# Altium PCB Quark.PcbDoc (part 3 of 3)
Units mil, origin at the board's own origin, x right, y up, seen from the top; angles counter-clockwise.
Board outline 1220.47 x 944.88 mil, 6 copper layers (Top1, Signal2, Gnd3, Power4, Signal5, Bottom6), stack 32.534 mil thick; 106 components, 182 nets, 776 pads, 404 vias.
Unrouted connection lines stored in the file: 82.
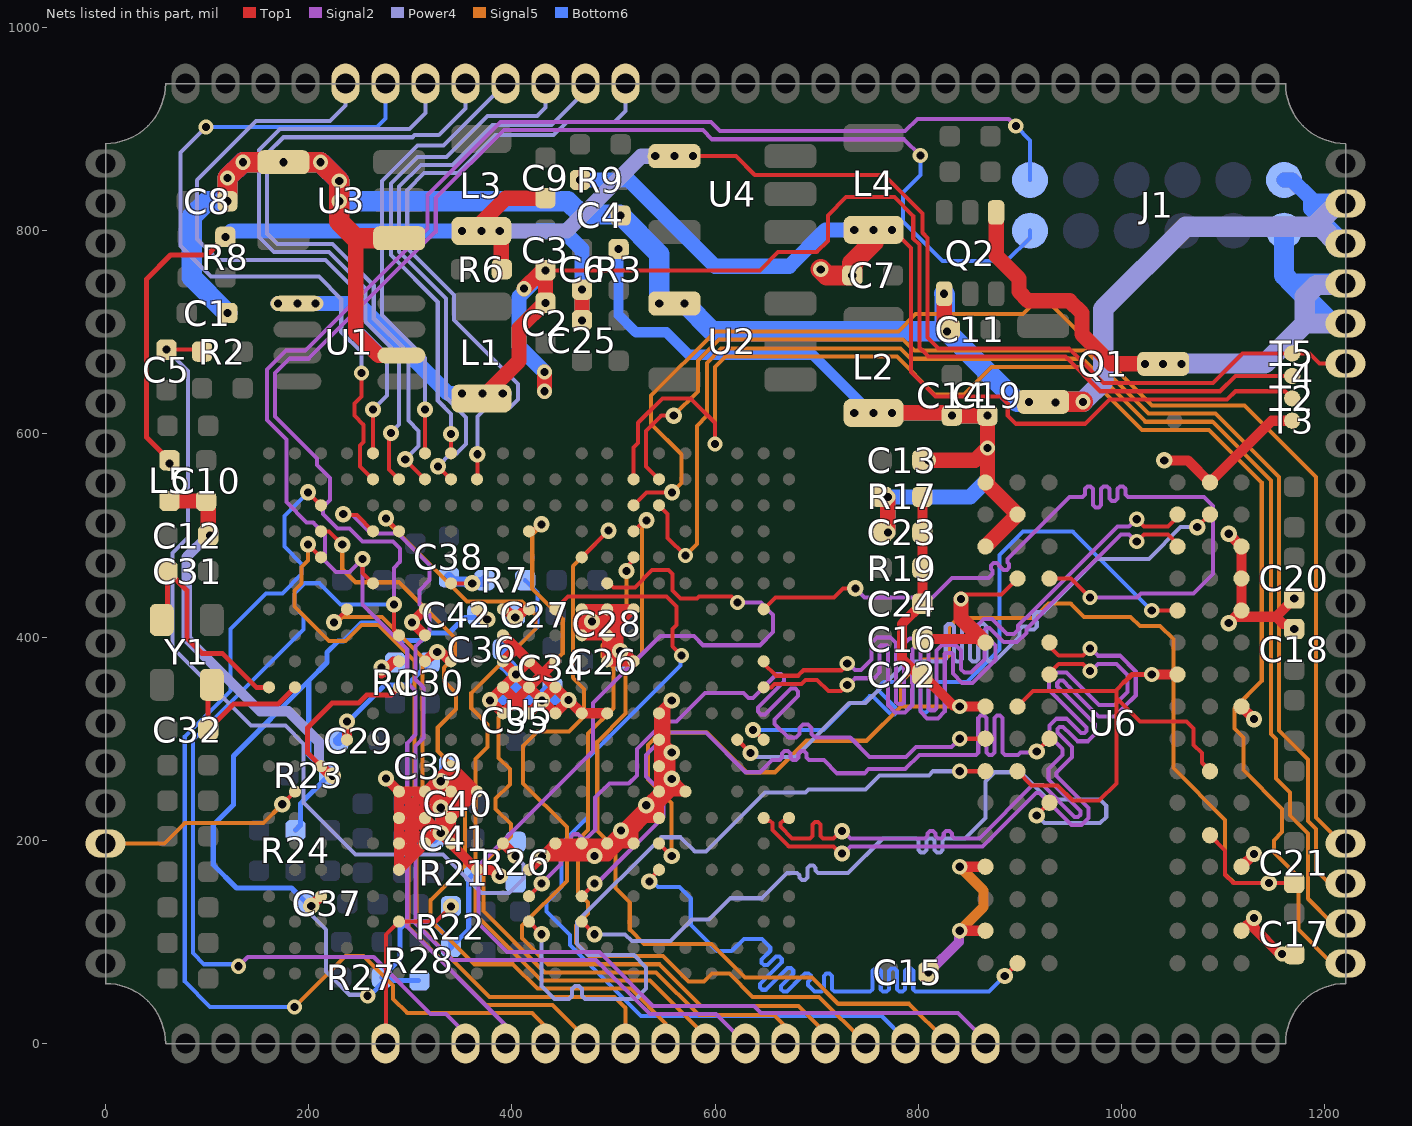
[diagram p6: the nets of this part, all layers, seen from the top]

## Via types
v1: diameter 16, hole 8, Top1 to Bottom6, tented both sides, 238 vias
v2: diameter 15, hole 8, Top1 to Bottom6, tented both sides, 166 vias

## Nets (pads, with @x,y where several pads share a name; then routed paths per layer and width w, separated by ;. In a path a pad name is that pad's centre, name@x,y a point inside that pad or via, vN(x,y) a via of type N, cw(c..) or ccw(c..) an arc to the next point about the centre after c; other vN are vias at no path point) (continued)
SDQ15: U5.M19 U6.B8 | length 793.5
  Top1 w4: U5.M19@621.77,299 v1(634.77,286) ; v1(1074.5,508.22) U6.B8@1087,520.72
  Power4 w4: v1(634.77,286) 638.77,282 679,282 732,335 748,335 789,376 823,376 824.6,376 827,378.4 827,410.6 829.4,413 832.6,413 835,410.6 835,378.4 837.4,376 840.6,376 843,378.4 843,410.6 845.4,413 848.6,413 851,410.6 851,378.4 853.4,376 856.6,376 859,378.4 859,410.6 861.4,413 864.6,413 867,410.6 867,378.4 869.4,376 870,376 875,376 897.5,398.5 899.62,400.62 899.62,403.45 899.62,407.69 902.45,410.52 906.69,410.52 908.11,409.11 909.52,407.69 913.76,407.69 916.59,410.52 916.59,414.76 915.18,416.18 913.76,417.59 913.76,421.83 916.59,424.66 920.83,424.66 921,424.5 923.5,424.5 976,477 1027,477 1058.22,508.22 v1(1074.5,508.22)
SDQM0: U5.M20 U6.E7 | length 757.4
  Top1 w4: v1@635.27,311.5 U5.M20@647.77,299 ; v2(1029.73,426.24) U6.E7@1055,426.24
  Bottom6 w4: v1(637.27,308.5) 706.5,308.5 733,335 739,335 743,335 745,335 747.83,337.83 751.79,341.79 755.18,341.79 773,323.97 776.4,323.97 778.66,326.23 778.66,329.63 760.84,347.45 760.84,350.84 764.8,354.8 766,356 770,356 778,356 783.6,356 786,353.6 786,332.8 788.4,330.4 791.6,330.4 794,332.8 794,353.6 796.4,356 799.6,356 802,353.6 802,328.4 804.4,326 807.6,326 810,328.4 810,353.6 812.4,356 815,356 848,356 880,388 880,481 903,504 951.97,504 v2(1029.73,426.24)
SDQM1: U5.G20 U6.D3 | length 839
  Top1 w4: U5.G20@647.77,427.36 659.41,439 717,439 726,448 v1(738,448) ; U6.D3@929.01,457.73 950.27,457.73 v2(969,439)
  Signal2 w4: v1(738,448) 747,439 814,439 833,458 869,458 872,461 873.13,462.13 873.13,465.53 871.56,467.1 871.56,470.49 873.82,472.75 877.22,472.75 880.49,469.49 883.75,466.22 887.15,466.22 889.41,468.48 889.41,471.87 887.84,473.45 887.84,476.84 890.76,479.76 949,538 961.6,538 964,540.4 964,546.04 966.4,548.44 969.6,548.44 972,546.04 972,529.96 974.4,527.56 977.6,527.56 980,529.96 980,546.04 982.4,548.44 985.6,548.44 988,546.04 988,536.31 990.4,533.91 993.6,533.91 996,536.31 996,546.04 998.4,548.44 1001.6,548.44 1004,546.04 1004,540.4 1006.4,538 1081,538 1090,529 1090,462 1071,443 1019,443 1015,439 v2(969,439)
SDQS0_N: U5.R21 U6.G3 | length 831.8
  Top1 w4: U5.R21@672.77,222 670.61,222 667.79,219.19 666.61,219.19 664.27,216.84 664.27,213.53 675.8,202 693.4,202 695.8,204.4 695.8,215.6 698.2,218 701.4,218 703.8,215.6 703.8,204.4 706.2,202 716.66,202 723.66,209 v1(725,209) ; U6.G3@929.01,361.96 U6.G3@929.01,363.24 929.01,364.53 938.19,373.71 962.01,373.71 v2(969.03,366.69)
  Signal2 w4: v1(725,209) 726.34,209 733.34,202 805,202 806.6,202 809,204.4 809,206.6 811.4,209 814.6,209 817,206.6 817,204.4 819.4,202 822.6,202 825,204.4 825,206.6 827.4,209 830.6,209 833,206.6 833,204.4 835.4,202 841,202 845,202 860,202 912.4,254.4 922.51,254.4 953.9,223.01 957.38,223.01 959.56,225.19 959.56,228.66 928.16,260.06 928.16,270.16 942,284 942,289.66 928.94,302.72 928.94,312.82 935.81,319.69 945.91,319.69 960.06,305.54 963.54,305.54 965.72,307.72 965.72,311.19 935.74,341.17 928.74,348.17 928.74,358.28 935.61,365.15 945.71,365.15 952.71,358.15 977.85,333 993,333 1006,346 1006,362.69 995,373.69 976.87,373.69 969.87,366.69 v2(969.03,366.69)
SDQS0_P: U5.R20 U6.F3 | length 831.8
  Top1 w4: U5.R20@647.77,222 649.94,222 652.75,219.19 653.93,219.19 656.27,216.84 656.27,210.22 672.49,194 716.66,194 723.66,187 v1(725,187) ; U6.F3@929.01,393.46 929.01,390.9 938.19,381.71 962.01,381.71 v2(968.98,388.69)
  Signal2 w4: v1(725,187) 726.34,187 733.34,194 863.31,194 915.72,246.4 919.19,246.4 950.59,215.01 960.69,215.01 967.56,221.88 967.56,231.98 936.16,263.37 936.16,266.85 951.09,281.78 951.09,291.88 936.94,306.03 936.94,309.5 939.12,311.69 942.6,311.69 950.28,304 956.75,297.54 966.85,297.54 973.31,304 973.72,304.4 973.72,314.51 943.74,344.49 936.74,351.49 936.74,354.96 938.92,357.15 942.39,357.15 949.39,350.15 977.54,322 993.31,322 1001.97,330.66 1014,342.69 1014,366 998.31,381.69 976.83,381.69 969.83,388.69 v2(968.98,388.69)
SDQS1_N: U5.J20 U6.B7 | length 832.2
  Top1 w4: U5.J20@647.77,376.18 647.77,374.23 660,362 681.81,362 687.19,367.39 724.39,367.39 v2@730,373 ; v2(1014.98,516) 1022,508.98 1045.81,508.98 1055,518.16 U6.B7@1055,520.72
  Signal2 w4: v2(730,374) 731.34,374 737.84,367.5 743.5,367.5 754,378 754,394.04 759.54,399.58 772.46,399.58 778,394.04 778,336.27 780.27,334 783.73,334 786,336.27 786,393.15 791.54,398.69 804.46,398.69 810,393.15 810,330 812,328 816,328 818,330 818,386.91 823.54,392.45 836.46,392.45 842,386.91 842,368.36 845.36,365 852,365 854.5,367.5 865,378 865,391.43 855.4,401.03 855.4,408.87 864.53,418 872.37,418 882.64,407.73 887.37,403 894,403 898.39,407.39 898.26,411.26 912.84,425.84 919.79,432.79 996,509 1007.13,509 1014.13,516 v2(1014.98,516)
SDQS1_P: U5.K20 U6.C7 | length 831.9
  Top1 w4: U5.K20@647.77,350.59 655.23,350.59 658.64,354 685.12,354 689.12,358 700.39,358 711.39,347 724,347 v2(730,353) ; v2(1015.02,494) 1022,500.98 1045.81,500.98 1055,491.79 U6.C7@1055,489.23
  Signal2 w4: v2(730,353) 731.34,353 737.84,359.5 756.46,359.5 762,365.04 762,390.73 ; 762.86,391.58 769.14,391.58 ; 770,390.73 770,332.96 776.96,326 787.04,326 794,332.96 794,387.84 796.16,390 799.84,390 802,387.84 802,326.69 808.69,320 819.31,320 826,326.69 826,383.6 ; 826.86,384.45 833.14,384.45 ; 834,383.6 834,364 843,355 853.31,355 876,377.69 876,391.74 864,403.74 864,406.16 866.84,409 870.05,409 884.05,395 897.31,395 906.39,404.07 906.39,408.07 916.15,417.84 927.79,429.47 999.31,501 1007.18,501 1014.18,494 v2(1015.02,494)
SODT0: U5.W11 U6.K1 | length 794.5
  Top1 w4: U5.W11@416.77,120 v1(429.27,107.5) ; v2(840.75,268) U6.K1@866.02,268
  Power4 w4: v1(429.27,107.5) 429.27,56.73 442,44 454,44 456,44 459,47 459,53.75 462,56.75 466,56.75 469,53.75 469,47 472,44 477,44 522,44 532,54 532,75 520,87 475,87 464,98 464,120 547,203 565.97,203 579.97,189 591,189 649,247 689,247 692,250 748,250 762,264 810.31,264 814.31,268 v2(840.75,268)
SODT1: U5.V11 U6.J1 | length 813.4
  Top1 w4: U5.V11@416.77,145 v1(429.27,157.5) ; v2(840.75,300) U6.J1@866.02,300
  Signal2 w4: v1(429.27,157.5) 446.39,174.61 448.06,176.29 448.06,180.53 443.82,184.77 443.82,189.02 446.64,191.84 450.89,191.84 457.25,185.48 460.23,182.5 464.47,182.5 467.3,185.33 467.3,189.57 464.32,192.55 457.96,198.91 457.96,203.16 460.79,205.99 465.03,205.99 469.27,201.74 473.51,201.74 478.46,206.69 482,210.23 482,242 496,256 515,256 523,264 523,290 550,317 562,317 590,345 628,345 631.5,341.5 632.91,340.09 637.16,340.09 660.53,363.46 664.77,363.46 667.6,360.63 667.6,356.39 642.11,330.89 642.11,326.87 645.15,323.82 649.18,323.82 674.67,349.32 678.91,349.32 681.74,346.49 681.74,342.25 658.37,318.87 658.37,314.63 660.5,312.5 672,301 677,301 679.4,301 683,304.6 683,310.4 686.6,314 691.4,314 695,310.4 695,304.6 698.6,301 707,301 709,301 733,301 752,282 787.69,282 797.69,292 832.75,292 v2(840.75,300)
SPI0_CLK: pad.52 U5.B16 | length 1223.8
  Top1 w4: U5.B16@544.77,555.32 532,568.09 532,603 547,618 v1(559.24,618)
  Signal5 w4: v1(559.24,618) 583,641.76 583,672.31 603.69,693 785,693 796,682 964.69,682 1026.69,620 1092.63,620 1155,557.63 1155,308 1183.5,279.5 1183.5,219.19 1191.5,211.19 1191.5,170.5 1201.66,160.34 1217.62,160.34 pad.52@1220.47,157.48
SPI0_CS: pad.50 U5.B15 | length 1410.3
  Top1 w4: U5.B15@519.77,555.32 519.77,586.77 524,591 524,611 548,635 576,635 600,611 v2(600,590)
  Signal5 w4: v2(600,590) 600,666 610,676 779,676 816,639 845,639 872,666 958.06,666 1020.06,604 1086,604 1138,552 1138,357 1111,330 1111,310 1120,301 1120,269 1158,231 1158,208 1150,200 1150,188 1174,164 1174,112 1207.26,78.74 pad.50@1220.47,78.74
SPI0_MISO: pad.51 U5.C16 | length 1347.2
  Top1 w4: U5.C16@544.77,529.72 553.3,521.2 553.3,497.77 v2(570.77,480.3)
  Signal5 w4: v2(570.77,480.3) 582,491.53 582,608 592,618 592,670 606,684 782.31,684 792.31,674 961.37,674 1023.37,612 1089.31,612 1147,554.31 1147,304.69 1152,299.69 1152,261 1166,247 1166,224.41 1183.5,206.91 1183.5,142.5 1207.89,118.11 pad.51@1220.47,118.11
SPI0_MOSI: pad.53 U5.C15 | length 1290.9
  Top1 w4: U5.C15@519.77,529.72 532.27,542.22 557.32,542.22 v1(557.65,542.52)
  Signal5 w4: v1(557.65,542.52) 567,551.87 567,580 537,610 537,637.69 600.31,701 780.31,701 797.31,718 903,718 912,727 931,727 1030,628 1121,628 1191.5,557.5 1191.5,222.5 1217.15,196.85 pad.53@1220.47,196.85
SRAS: U5.V13 U6.J3 | length 794.7
  Top1 w4: U5.V13@468.77,145 v1(481.27,157.5) ; v1(916.51,287.5) U6.J3@929.01,300
  Signal2 w4: v1@483.5,157.5 549,223 549,246 532,263 532,284 554.12,306.12 590.88,306.12 630,267 644,267 656,279 662,279 663.6,279 666,281.4 666,285.6 668.4,288 671.6,288 674,285.6 674,281.4 676.4,279 679.6,279 682,281.4 682,285.6 684.4,288 687.6,288 690,285.6 690,281.4 692.4,279 698,279 699,279 707,279 720,266 747,266 751.12,270.12 787.12,270.12 801,284 855,284 856.6,284 859,286.4 859,320.6 861.4,323 864.6,323 867,320.6 867,286.4 869.4,284 872.6,284 875,286.4 875,320.6 877.4,323 880.6,323 883,320.6 883,286.4 885.4,284 887,284 898,284 900.62,286.62 915.63,286.62 v1(916.51,287.5)
SRST: U5.U16 U6.T2 | length 757.8
  Top1 w4: v1@532.27,158.5 U5.U16@544.77,171 ; v1(885.01,66.5) U6.T2@897.51,79
  Bottom6 w4: v1(535.27,159.5) 538.11,159.5 543.61,154 565,154 576,143 576,117 602,91 616.37,91 628.37,103 646,103 654.29,94.71 654.29,91.32 645.83,82.86 645.83,79.47 648.09,77.2 651.49,77.2 659.95,85.66 663.34,85.66 665.6,83.4 665.6,80 644.15,58.55 644.15,55.16 646.41,52.9 649.81,52.9 671.26,74.35 674.65,74.35 676.92,72.08 676.92,68.69 664.88,56.65 664.88,53.26 667.14,51 670.54,51 684.27,64.73 688.54,69 691.94,69 694.2,66.74 694.2,63.35 691.62,60.77 691.62,57.38 698,51 704.6,51 707,53.4 707,66.6 709.4,69 712.6,69 715,66.6 715,53.4 717.4,51 752.6,51 755,53.4 755,71.6 757.4,74 760.6,74 763,71.6 763,53.4 765.4,51 768.6,51 771,53.4 771,71.6 773.4,74 776.6,74 779,71.6 779,53.4 781.4,51 784.6,51 787,53.4 787,71.6 789.4,74 792.6,74 795,71.6 795,53.4 797.4,51 869.51,51 v1(885.01,66.5)
SVREF: C21.2 C22.2 C23.1 C24.2 R17.1 R19.2 U5.T16 U6.H1 U6.M8 | length 1527.1
  Top1 w4: U5.T16@544.77,197 v1(557.27,184.5) ; U6.M8@1087,205 1102,190 1102,166 1110,158 v1(1145,158) C21.2@1170,158
  Top1 w10: C22.2@800.5,362.5 784,379 784,413 C24.2@804,433 R19.2@804,468 C23.1@804,503 R17.1@804,538 ; C22.2@804,363 834.3,332.7 839.79,332.7 v2(840.75,331.75) ; v2@841.25,331.75 U6.H1@866.02,331.75
  Signal5 w4: v1(557.27,184.5) 557.27,236.73 534,260 534,294 546,306 592,306 631,267 659,267 690,298 749,298 782.75,331.75 ; v2(840.75,331.75) 782.75,331.75 ; v1(1145,158) 1111,158 1102,167 1102,220 1051,271 1051,398 1038,411 1018,411 1009,420 963,420 950,433 928,433 914,419 839,419 830,410 830,382 826,378 805,378 782.75,355.75 782.75,331.75
SWE: U5.W13 U6.L3 | length 794.8
  Top1 w4: U5.W13@468.77,120 v1(481.27,107.5) ; v1(916.51,224.5) U6.L3@929.01,237
  Power4 w4: v1(481.27,107.5) 511.5,107.5 518,101 556.04,101 577.04,122 594,122 615,143 646,143 668,165 670.83,167.83 671,168 675,168 680.6,168 683,165.6 683,163.38 685.4,160.98 688.6,160.98 691,163.38 691,168 691,172.62 693.4,175.02 696.6,175.02 699,172.62 699,170.4 701.4,168 707,168 731,168 765,202 797.6,202 800,199.6 800,190.4 802.4,188 805.6,188 808,190.4 808,199.6 810.4,202 813.6,202 816,199.6 816,190.4 818.4,188 821.6,188 824,190.4 824,199.6 826.4,202 846,202 866,222 866,258 875,267 900.69,267 927.69,240 979,240 985,234 985,223 979,217 924.01,217 v1(916.51,224.5)
UART0_RX: J1.1 pad.29 U5.H6 | length 2169.5
  Top1 w4: v1(284,432) 284,406.59 U5.H6@288.82,401.77
  Signal2 w4: v2(131,76) 140,85 264,85 320,29 335,29 354.33,9.67 pad.29@354.33,0 ; v1(284,432) 284,468.2 290,474.2 290,487 283,494 253,494 240,507 228.2,507 214.1,521.1 214.1,528.1 221,535 221,556.56 208,569.56 208,576 167,617 167,660 181,674 200,674 325,799 325,832 392,899 588,899 597,890 786,890 v2(802,874)
  Bottom6 w4: v2(131,76) 129,78 97,78 86,89 86,298.69 195,407.69 195,421 186,430 186,443 196,453 210.44,453 231.44,432 v1(284,432) ; v2(802,874) 802,855 784.83,837.83 784.83,808.98 823.82,770 887,770 910,793 J1.1@910,800
UART0_TX: J1.2 pad.30 U5.F5 | length 1760.5
  Top1 w4: v1(253,477) 253,463.18 U5.F5@263.23,452.95
  Signal2 w4: pad.30@393.7,0 393.7,17.99 297,114.69 297,296 305,304 305,347 297,355 297,388 253,432 v1(253,477) 240,464 227,464 216,475 216,501.44 204.44,513 198,513 178,533 178,594.69 159,613.69 159,663.31 177.69,682 196.69,682 317,802.31 317,835.31 388.69,907 596,907 605,898 787,898 799,910 889,910 v2(896,903)
  Bottom6 w4: v2(896,903) 910,889 J1.2@910,850
UART1_CTS: pad.32 U5.E3 | length 727.9
  Top1 w4: v1(199.25,491.34) U5.E3@212.05,478.54
  Signal5 w4: v1(199.25,491.34) 199.25,475.25 193,469 193,453 186,446 186,430 220,396 236,396 252,412 268.69,412 304,376.69 304,202.31 298,196.31 298,114.69 374.69,38 440,38 472.44,5.56 pad.32@472.44,0
UART1_RTS: pad.31 U5.C3 | length 1012.5
  Top1 w4: v1(199.25,542.52) U5.C3@212.05,529.72
  Signal5 w4: v2(186,36) 236,86 253.91,86 283,56.91 283,44 297,30 420,30 433.07,16.93 pad.31@433.07,0
  Bottom6 w4: v2(186,36) 103,36 78,61 78,302 123,347 123,408 158,443 174,443 193,462 193,472 176,489 176,519.27 v1(199.25,542.52)
UART1_RX: pad.34 U5.D3 | length 802.8
  Top1 w4: U5.D3@212.05,504.13 219.87,504.13 v1(233,491)
  Signal2 w4: v1@232.89,491 v1(233,491)
  Signal5 w4: v1(233,491) 233,467 246,454 289,454 344,399 344,380.88 333,369.88 333,357 345,345 345,329 327,311 327,288 354,261 354,175 320,141 320,121 363,78 401,78 425,54 517,54 551.18,19.82 pad.34@551.18,0
UART1_TX: pad.33 U5.G4 | length 663.9
  Top1 w4: v1(224.84,414.57) U5.G4@237.64,427.36
  Signal5 w4: v1(224.84,414.57) 227.77,414.57 233.21,420 272,420 312,380 312,199 306,193 306,118 378,46 501,46 511.81,35.19 pad.33@511.81,0
UART2_CTS: pad.38 U5.E13 | length 884
  Top1 w4: U5.E13@468.77,478.54 v1(495,504.77)
  Signal5 w4: v1(495,504.77) 460,469.77 460,360 471,349 471,322 456,307 425,307 411,293 411,256 454,213 454,160 410,116 410,103.63 435.63,78 545.31,78 586.31,37 682,37 708.66,10.34 pad.38@708.66,0
UART2_RTS: pad.35 U5.D6 | length 821.8
  Top1 w4: v1(276.02,516.93) U5.D6@288.82,504.13
  Signal5 w4: v1(276.02,516.93) 276.02,514.98 356,435 410,435 423,422 423,408 360,345 360,330 376,314 376,292 364,280 364,127 429,62 536,62 590.55,7.45 pad.35@590.55,0
UART2_RX: pad.36 U5.D5 | length 888.6
  Top1 w4: v1@234,520 247.36,520 U5.D5@263.23,504.13
  Signal2 w4: v1@234,520 243.18,520 261.18,502 288,502 319,471 319,456 309,446 309,432 319,422 319,405 305,391 305,358.31 313,350.31 313,300.69 305,292.69 305,118 341,82 482.69,82 535.69,29 600.92,29 pad.36@629.92,0
  other v1: 234,521
UART2_TX: pad.37 U5.D11 | length 829.5
  Top1 w4: U5.D11@416.77,504.13 419.13,504.13 v1@430,515
  Signal5 w4: v1(429,511) 429,509.66 420,500.66 420,448 450,418 450,384 387,321 387,281 398,270 398,255 384,241 384,231 399,216 399,204 372,177 372,130.31 432.31,70 542,70 584,28 658,28 669.29,16.71 pad.37@669.29,0
UART3_CTS: pad.41 U5.D15 | length 813.5
  Top1 w4: U5.D15@519.77,504.13 v1@532.57,516.93
  Signal5 w4: v1(532.57,514.93) 528,510.36 528,384 512,368 512,325 484,297 484,209 502,191 502,153 516,139 516,112 530,98 596.31,98 629.31,65 695.31,65 721.19,39.12 791,39.12 826.77,3.35 pad.41@826.77,0
UART3_RTS: pad.42 U5.F14 | length 1245.1
  Top1 w4: U5.F14@493.77,452.95 495.94,452.95 499.89,449 521,449 538,466 554,466 558,462 558,446 566,438 582,438 584,440 616,440 v2(622,434)
  Signal2 w4: v2(622,434) 645,434 657,422 657,405 644,392 588,392 579,401 546,401 480,335 480,288 367,175 367,118 395,90 486,90 539,37 638.37,37 645.37,30 839,30 866.14,2.86 pad.42@866.14,0
UART3_RX: pad.40 U5.G12 | length 904.3
  Top1 w4: U5.G12@442.77,427.36 455.41,440 552,440 562,430 562,412 558,408 558,391 v2(567,382)
  Bottom6 w4: v2(567,382) 565.95,380.95 565.95,371.95 475,281 475,223 449,197 449,154 434,139 434,130 457,107 457,97 527,27 764,27 787.4,3.6 pad.40@787.4,0
UART3_TX: pad.39 U5.E15 | length 753.3
  Top1 w4: v1(512.77,465) 515.07,467.3 515.07,471.67 519.77,476.38 U5.E15@519.77,478.54
  Signal5 w4: v1(512.77,465) 512.77,415.77 489,392 489,381 500,370 500,330 475,305 475,210 465,200 465,149 475,139 475,128 463,116 463,99 476,86 548.63,86 573.63,61 589,61 597,69 614,69 637,46 702.34,46 748.03,0.31 pad.39@748.03,0
UBOOT: pad.27 R22.1 U5.W6 | length 182.4
  Top1 w4: pad.27@276,0.41 276,107.18 U5.W6@288.82,120 325.2,120 v1(340.1,134.9)
USB0-DRVVBUS: pad.18 U5.P2 | length 207.6
  Top1 w4: v1(173.96,235.5) U5.P2@186.46,248
  Signal5 w4: pad.18@0,196.85 57.85,196.85 78,217 155.46,217 v1(173.96,235.5)
USB-DM0: pad.93 U5.B5 | length 720.7
  Top1 w4: v2(252,660) 252,637 245,630 245,618 254,609 254,592 250.43,588.43 250.43,568.11 U5.B5@263.23,555.32
  Power4 w4: v2(99,902) 74,877 74,785 104,755 210,755 232,733 232,700.43 252,680.43 v2(252,660)
  Bottom6 w4: v2(99,902) 267,902 275.59,910.59 pad.93@275.59,944.88
USB-DM1: pad.91 U5.B7 | length 665.7
  Top1 w4: v1(295,575) 295,574.72 U5.B7@314.41,555.32
  Power4 w4: v1(295,575) 308,588 308,603 298,613 298,679.69 264,713.69 264,746.25 223.25,787 169.31,787 159,797.31 159,876 175,892 302.31,892 304.31,894 328,894 354.33,920.33 pad.91@354.33,944.88
USB-DM2: pad.89 U5.A8 | length 496.9
  Top1 w4: U5.A8@340,580.91 v1(340,599.91)
  Power4 w4: v1(340,599.91) 340,619.69 327,632.69 327,730 281,776 281,792.81 281,846.69 307.03,872.72 335.72,872.72 375.91,912.91 424.91,912.91 433.07,921.07 pad.89@433.07,944.88
USB-DM3: pad.87 U5.B9 | length 634.2
  Top1 w4: U5.B9@365.59,555.32 366,555.72 v1(366,580)
  Power4 w4: v1(366,580) 366,617 375,626 398,626 406,634 406,649 343,712 343,736.63 297,782.63 297,840.06 313.66,856.72 346.72,856.72 384,894 441,894 454,907 501,907 511.81,917.81 pad.87@511.81,944.88
USB-DP0: pad.94 U5.A5 | length 612.4
  Top1 w4: U5.A5@263.23,580.91 v1(263.23,624)
  Power4 w4: pad.94@236.22,944.88 236.22,923.22 221,908 148.31,908 90,849.69 90,791.63 110.63,771 216.63,771 248,739.63 248,707.06 277,678.06 277,637.77 v1(263.23,624)
USB-DP1: pad.92 U5.B6 | length 629
  Top1 w4: v1(281,601) 279,599 279,565.13 U5.B6@288.82,555.32
  Power4 w4: v1(281,601) 281,601.34 289,609.34 289,677.37 256,710.37 256,742.94 219.94,779 166,779 151,794 151,879.31 171.69,900 299,900 314.96,915.96 pad.92@314.96,944.88
USB-DP2: pad.90 U5.A7 | length 447.1
  Top1 w4: U5.A7@314.41,580.91 v1(314.41,624)
  Power4 w4: v1(314.41,624) 314.41,674.59 272,717 272,823.18 272,849 307.03,884.03 332.85,884.03 pad.90@393.7,944.88
USB-DP3: pad.88 U5.B8 | length 565.5
  Top1 w4: v1(327.2,568.11) U5.B8@340,555.32
  Power4 w4: v1(327.2,568.11) 340.09,581 346,581 355,590 355,616 335,636 335,733.31 289,779.31 289,843.37 310.35,864.72 341.72,864.72 381,904 439,904 472.44,937.44 pad.88@472.44,944.88
VCC-DRAM: C13.2 C14.2 C15.2 C16.2 C17.2 C18.2 C19.2 C20.2 C23.2 L2.2 R3.1 R17.2 T3.0 U5.L16 U5.M16 U5.N16 U5.P16 U5.P17 U5.R16 U5.T12 U5.T13 U5.T14 U5.T15 U5.U11 U6.A1 U6.A8 U6.B2 U6.C1 U6.C9 U6.D2 U6.D9 U6.E9 U6.F1 U6.G7 U6.H2 U6.H9 U6.K2 U6.K8 U6.N1 U6.N9 U6.R1 U6.R9 | length 3199.4
  Top1 w4: v2(842.09,437.5) 842.5,437.5 847,442 881.78,442 U6.D2@897.51,457.73 ; U6.K2@897.51,268 911.51,254 937,254 952,239 978,239 995,256 995,340 ; U6.H2@897.51,331.75 912.76,347 994,347 995,348 ; 1002.62,355.62 995,348 ; U6.K8@1087,264.75 U6.K8@1087,268 1087,268.34 1079,276.34 1079,286 1071,294 1071,310 1064,317 1018,317 995,340 ; v1(1130.5,186.5) v1@1130.5,187.34 ; 995,340 995,348
  Top1 w5: 1002.62,355.62 1010.24,363.24 v2(1029.73,363.24)
  Top1 w10: U5.U11@416.77,171 v1(429.77,184) ; 474.77,190.5 436.27,190.5 ; v1(557.27,337.5) 551.02,331.25 ; U5.P17@570.77,248 U5.P17@570.23,248 ; C16.2@810,398 861.13,398 864.39,394.74 865.75,394.74 U6.F1@866.02,394.74 ; v2(840.75,111) U6.R1@866.02,111 ; v2(840.75,174) U6.N1@866.02,174 ; v2(1029.73,363.24) U6.G7@1055,363.24 ; v1(1042,574) 1065.22,574 U6.A8@1087,552.22 1147.78,613 T3.0@1168,613 ; v1(1105.5,413.74) 1111.75,419.99 ; v1(1105.5,501.73) U6.C9@1118,489.23 U6.D9@1118,457.73 U6.E9@1118,426.24 1111.75,419.99 ; U6.R9@1118,111 v1(1130.5,123.5) 1130.5,113.5 1156,88 v2(1158,88) C17.2@1170,88 ; U6.N9@1118,174 v1(1130.5,186.5) ; U6.H9@1118,331.75 v1(1130.5,319.25) ; v2(1170,408) 1165,413 1158.97,413 1151.99,419.99 ; v2(1170,438) 1151.99,419.99 ; v1(429.77,184) 436.27,190.5 ; v1(429.77,184) 494.27,184 507.27,197 ; 436.27,190.5 U5.T12@442.77,197 U5.T13@468.77,197 ; U5.T13@468.77,197 v1(481.27,184.5) 482.27,184.5 U5.T14@494.77,197 ; U5.T13@468.77,197 U5.T14@493.77,197 U5.T14@494.77,197 ; U5.T14@494.77,197 v1(507.27,209.5) ; U5.T14@494.77,197 507.27,197 ; 507.27,197 U5.T15@519.77,197 ; 507.27,197 513.52,203.25 ; v1(507.27,209.5) v1(532.27,234.5) ; v1(507.27,209.5) 513.52,203.25 ; 513.52,203.25 U5.T15@519.77,197 ; U5.T15@519.77,197 519.77,210.27 ; 519.77,210.27 531.5,222 ; 519.77,210.27 519.77,218 523.77,222 531.5,222 ; 531.5,222 U5.R16@544.77,222 ; 531.5,222 538.14,228.64 ; v1(532.27,234.5) 538.14,228.64 ; v1(532.27,234.5) 532.27,235.5 U5.P16@544.77,248 ; 538.14,228.64 U5.R16@544.77,222 ; 538.14,228.64 544.77,235.27 ; U5.R16@544.77,222 544.77,235.27 ; 544.77,235.27 U5.P16@544.77,248 ; 544.77,235.27 557.5,248 ; U5.P16@544.77,248 v1(557.27,260.5) ; U5.P16@544.77,248 557.5,248 ; U5.P16@544.77,248 U5.N16@544.77,273 ; U5.N16@544.77,273 v1(557.27,260.5) ; U5.N16@544.77,273 v1@556.12,284.35 ; U5.N16@544.77,273 U5.M16@544.77,299 ; U5.M16@544.77,299 U5.L16@544.77,325 551.02,331.25 ; U5.M16@544.77,299 v1(557.27,286.5) ; 551.02,331.25 551.02,294.37 557.27,288.12 v1(557.27,286.5) ; v1@556.12,284.35 557.27,285.5 v1(557.27,286.5) ; v1@556.12,284.35 556.12,285.35 v1(557.27,286.5) ; v1@556.12,284.35 556.12,281.11 555.77,280.76 555.77,263.62 557.27,262.12 v1(557.27,260.5) ; v1(557.27,260.5) 568.77,249 569.23,249 U5.P17@570.23,248 ; 557.5,248 U5.P17@570.23,248 ; 1111.75,419.99 1151.99,419.99
  Top1 w15: v2(756,620.72) v2(774,620.72) 830.28,620.72 v2(833,618) v2(868,618) ; v2(770,503) v2(770,538) ; v2(810,574) 855.76,574 v2(868,586.24) ; v2(842.09,437.5) 842.09,418.39 U6.F1@865.75,394.74 ; C19.2@865.28,620.72 v2(868,618) ; U6.C1@866.02,489.23 U6.B2@897.51,520.72 U6.A1@866.02,552.22 866.02,552.49 868,554.48 v2(868,586.24) ; v2(868,586.24) v2(868,618)
  Signal2 w10: v2(810,70) 839.96,99.96 839.96,110.22 v2(840.75,111)
  Signal5 w10: v2(840.75,111) 864,134.25 864,150.75 v2(840.75,174)
  Bottom6 w10: v2(505,782) 505,717 522,700 552,700 574,678 696,678 v2@753.28,620.72
  Bottom6 w15: v2(737,620.72) 753.28,620.72 v2(756,620.72) v2(774,620.72) 830.28,620.72 v2(833,618) v2(868,618) v2(868,586.24) 868,555 851,538 v2(770,538) v2(770,503)
VDD1V1-EPHY: C38.2 R7.2 U5.F8 | length 59.8
  Top1 w4: U5.F8@340,452.95 v1(361,452.95)
  Bottom6 w10: C38.2@338,459 342.29,454.71 354.62,454.71 356.38,452.95 358,452.95 359.15,454.1 371.1,454.1 R7.2@373,456
VDD1V2-SYS: C7.2 C34.2 C35.2 C36.2 L4.2 R7.1 R9.2 T2.0 U5.H10 U5.J10 U5.J11 U5.J12 U5.K10 U5.K11 U5.K12 U5.L10 U5.L11 U5.L12 U5.L13 U5.L14 | length 1843
  Top1 w4: v2(756,800.72) 756.91,799.82 776.18,799.82 793,783 793,661 817,637 881,637 888,630 888,618 896,610 964,610 988,634 1104,634 1112,642 1161,642 T2.0@1168,635
  Top1 w10: U5.K10@391.18,350.59 403.98,337.8 ; U5.H10@391.18,401.77 391.59,401.77 404.28,389.08 ; U5.J11@416.77,376.18 v1@403.98,363.39 ; U5.J12@442.77,376.18 429.98,363.39 ; U5.L13@468.36,325 U5.L13@468.77,325 U5.L14@493.77,325 ; U5.L13@468.57,325.2 v1(455.77,338) ; 403.98,337.8 U5.L11@416.77,325 v1(429.57,337.8) ; 403.98,337.8 U5.L10@391.18,325 v1(378.39,337.8) v1(403.98,363.39) ; 403.98,337.8 U5.K11@416.77,350.59 ; v1(403.98,363.39) U5.K11@416.77,350.59 ; v1(403.98,363.39) U5.J10@391.18,376.18 391.39,376.18 404.28,389.08 ; 404.28,389.08 416.98,376.39 429.98,363.39 ; U5.K11@416.77,350.59 v1(429.57,337.8) ; U5.K11@416.77,350.59 417.18,350.59 429.98,363.39 ; v1(429.57,337.8) 442.36,350.59 U5.K12@442.77,350.59 ; v1(429.57,337.8) 442.36,325 U5.L12@442.77,325 v1(455.77,338) ; 429.98,363.39 U5.K12@442.77,350.59 ; U5.K12@442.77,350.59 455.36,338 v1(455.77,338)
  Top1 w20: v2(704,762) 710,756 v2(735,756) 735,768 756,789 v2(756,800.72)
  Signal5 w15: v2(737,800.72) v2(756,800.72) v2(774,800.72)
  Power4 w15: v2(737,800.72) v2(756,800.72) v2(774,800.72)
  Bottom6 w4: C36.2@391,388 392.66,389.66 404.66,389.66 425,410 425,444 R7.1@413,456
  Bottom6 w10: v1(378.39,337.8) 378.59,338 C35.2@404,338 428,338 v1(455.77,338)
  Bottom6 w15: C36.2@391,388 393.5,385.5 393.5,373.86 v1(403.98,363.39) C35.2@404,338 ; v1@428,338 C34.2@440,350 ; v2(467,850) 515,850 600,765 673,765 708.72,800.72 v2(737,800.72) v2(756,800.72) v2(774,800.72) ; v2(704,762) 710,756 v2(735,756)
VDD-CPUS: C29.2 C30.2 U5.J7 U5.J8 U5.M4 | length 181.4
  Top1 w10: U5.M4@237.64,299 237.64,309.83 v1(237.64,317) ; U5.J7@314.41,376.18 314.95,376.18 322.9,384.13 v1@325.36,384.13 ; v1(326.51,385.28) v1@325.36,384.13 ; U5.J8@340,376.18 339.46,376.18 331.51,384.13 v1@325.36,384.13
  Bottom6 w5: v1@236.49,315.85 237.85,315.85 275,353 297,353 C30.2@319,375
  Bottom6 w10: C29.2@229,298 236.49,305.49 236.49,315.85 v1(237.64,317)
VDD-CPUX: C2.2 C3.2 C39.2 C40.2 C41.2 L1.2 R26.2 T4.0 U1.5 U5.N8 U5.P6 U5.P7 U5.P8 U5.P9 U5.R6 U5.R7 U5.R8 U5.T6 U5.T7 U5.T8 U5.U6 U5.U9 | length 2684.4
  Top1 w4: v1@327.5,209.5 v1(329.9,207.1) U5.T8@340,197 ; v1@327.5,234.5 v1(329.9,232.1) U5.R8@340,222 ; v1@327.5,260.5 v1(329.9,258.1) U5.P8@340,248 ; v2(433,761) 644,761 662,779 700,779 711,790 711,815 729,833 776.69,833 795,814.69 795,792.31 801,786.31 801,685 810,676 945,676 979,642 1097,642 1112,657 T4.0@1168,657
  Top1 w10: v1(276.02,260.8) U5.P6@288.82,248 ; U5.R6@288.82,222.18 U5.P6@288.82,247.77 ; U5.R6@289,222.18 U5.R6@288.82,222 ; U5.R6@290.36,221 289.36,222 U5.R6@289,222 ; U5.R6@290.41,221 299.56,211.85 301.7,209.7 ; 301.73,236.27 301.73,234.86 ; v1@327.5,234.5 v1@327,235 ; v1(329.9,207.1) v1@329.9,212.08 ; v1(329.9,258.1) 329.9,248 ; U5.T8@340,197 U5.R8@340,222 ; U5.N8@341.54,272 340.54,273 U5.N8@340,273 ; U5.N8@341.59,272 349.3,264.3 ; 349.3,232.7 349.3,248 ; v1(388,165) 386.38,165 380.38,171 U5.U9@365.59,171 329.7,206.9 v1@327.2,209.39 ; U5.T6@288.82,197 U5.U6@288.82,171 v1@327.2,209.39 ; U5.T6@288.82,197 U5.R6@288.82,222 ; U5.T6@288.82,197 289,197 301.7,209.7 ; U5.T6@288.82,197 301.73,184.09 301.73,209.68 U5.T7@314.41,197 U5.R7@314.41,222 U5.R7@314.41,222.18 ; U5.R6@288.82,222 U5.R6@289,222 ; U5.P6@288.82,247.77 U5.P6@288.82,248 ; U5.P6@288.82,247.77 301.73,234.86 ; U5.P6@288.82,248 U5.P7@314.41,248 ; U5.R6@289,222 301.73,234.73 ; 301.73,209.73 301.73,234.73 ; 301.73,209.73 U5.R7@314.3,222.3 ; 301.73,234.73 301.8,234.8 ; 301.73,234.73 301.73,234.86 ; 301.73,234.86 301.8,234.8 ; 301.8,234.8 U5.R7@314.3,222.3 ; 301.8,234.8 U5.P7@314.41,247.41 ; U5.R7@314.3,222.3 U5.R7@314.41,222.41 ; U5.R7@314.3,222.3 U5.R7@314.41,222.18 ; U5.R7@314.41,222.18 U5.R7@314.41,222.41 ; U5.R7@314.41,222.18 314.5,222.09 v1@327.2,209.39 ; U5.R7@314.41,222.41 U5.P7@314.41,247.41 ; U5.R7@314.41,222.41 v1@327,235 ; U5.P7@314.41,247.41 U5.P7@314.5,247.5 ; U5.P7@314.41,247.41 U5.P7@314.41,247.59 ; U5.P7@314.41,247.59 U5.P7@314.5,247.5 ; U5.P7@314.41,247.59 U5.P7@314.41,248 ; U5.P7@314.41,248 U5.P7@315,248 ; U5.P7@314.5,247.5 v1@327,235 ; U5.P7@314.5,247.5 U5.P7@315,248 ; U5.P7@315,248 327.5,260.5 U5.N8@340,273 ; U5.P7@315,248 329.9,248 ; v1@327,235 v1@329.9,237.9 ; v1@327.2,209.39 v1@329.9,212.08 ; v1@329.9,212.08 339.82,222 U5.R8@340,222 ; v1@329.9,212.08 v1(329.9,232.1) v1@329.9,237.9 ; v1@329.9,237.9 U5.P8@340,248 ; v1@329.9,237.9 329.9,248 ; 329.9,248 U5.P8@340,248 ; U5.R8@340,222 365.59,247.59 U5.P9@365.59,248 ; U5.R8@340,222 U5.P8@340,248 ; U5.P8@340,248 349.3,248 ; U5.P8@340,248 U5.N8@340,273 ; 349.3,248 U5.P9@365.59,248 ; 349.3,248 349.3,264.3 ; 349.3,264.3 U5.P9@365.59,248
  Top1 w15: L1.2@370,634.72 407,671.72 407,704 433,730 v2(433,761) 430.5,758.5 427.5,758.5 v2(412,743) ; v2(432,642) v2(432,661)
  Signal2 w10: v2(432,642) v2(432,661)
  Signal5 w10: v2@415,743 v2(433,761) ; v2(432,642) v2(432,661)
  Power4 w10: v2@415,743 v2(433,761)
  Bottom6 w10: C41.2@323,202 328,207 328,210.96 329.9,212.86 v1(329.9,232.1) v1(329.9,258.1) 329.9,259.72 333,262.82 333,268 C39.2@338,273
  Bottom6 w15: v2(169.82,728.39) v2(188.82,728.39) v2(206.82,728.39) 248.61,728.39 337.28,639.72 v2(351,639.72) v2(371,639.72) v2(391,639.72) v2@392,639.72 ; v2(432,642) v2(432,661) 407,686 407,735 v2(433,761)
  other v2: 433,729
VDD_5V: C1.2 C4.2 C8.2 C11.2 J1.12 pad.68 pad.69 Q1.2 Q2.4 U1.2 U2.4 U3.1 U3.4 | length 2285.8
  Top1 w15: 246.4,792.6 246.4,699.6 268.8,677.2 U1.2@291.18,677.2 ; v2(825.41,738) 825.41,708.59 C11.2@831,703
  Top1 w20: v2(120,829) v2(120,852) v2(135.4,867.4) v2(175.06,867.4) v2(211.6,867.4) v2(230,849) v2(230,829) 230,809 246.4,792.6 U3.1@289.06,792.6 ; Q1.2@922.94,631.6 v2(962,631.6)
  Power4 w20: v2(909,631.6) v2(962,631.6) 982,651.6 982,723 1063,804 1189.75,804 ; pad.68@1213.12,783.91 pad.68@1216.61,787.4 ; pad.68@1220.47,787.4 pad.68@1216.61,787.4 ; pad.69@1220.47,826.77 1212.52,826.77 1189.75,804 ; 1189.75,804 1195.92,804 1212.52,787.4 pad.68@1216.61,787.4
  Bottom6 w15: J1.12@1160,850 1168,850 1186.35,831.65 1186.35,829.17 ; pad.68@1212.61,785.96 pad.68@1219.03,785.96 ; pad.68@1220.47,787.4 1186.35,821.52 1186.35,829.17 ; pad.69@1220.47,826.77 1218.07,829.17 1186.35,829.17
  Bottom6 w20: v2(120,719) 85,754 85,814 100,829 v2(120,829) v2(120,852) v2(135.4,867.4) v2(175.06,867.4) v2(211.6,867.4) v2(230,849) v2(230,829) 455,829 468,816 506,816 v2(507,815) 545,777 v2(545,728.4) v2(570,728.4) 597.4,701 824.28,701 v2@826.14,702.86 ; v2(825.41,738) 826.14,737.27 v2@826.14,702.86 ; v2(962,631.6) v2(909,631.6) 897.4,631.6 v2@826.14,702.86 ; pad.68@1219.03,785.96 pad.68@1220.47,787.4
  other v2: 935,631 828.2,700.8
VDD_AV_3.3V: C10.2 C12.2 C37.1 C42.2 L5.2 R21.2 R22.2 R23.2 R24.2 R27.1 R28.1 U5.G9 U5.K6 U5.N3 U5.V3 | length 1684.4
  Top1 w4: v1@199.55,132.5 v1(202.55,135.5)
  Top1 w5: U5.N3@212.05,273 199,286.05 199,311 223,335 249,335 257,343 281.23,343 U5.K6@288.82,350.59
  Top1 w10: v1(202.55,135.5) U5.V3@212.05,145 ; U5.N3@212.05,273 v1@222.55,262.5 ; U5.G9@365.59,427.36 v1(375.69,417.26)
  Top1 w15: L5.2@63,534 C10.2@99,534 ; C12.2@101,500 C10.2@101,532
  Power4 w4: v1(202.55,135.5) 202.55,126.45 217,112 217,71 240,48 253,48 v2@257,44
  Power4 w10: v2@101,500 80,479 80,399 152,327 180,327 210,297 210,277.05 v1(223.55,263.5)
  Bottom6 w5: R24.2@187,210 192,215 192,236 R23.2@220,264 200,284 200,357 ; C37.1@198,138 183,153 129,153 106,176 106,215 126,235 126,283 200,357 ; v2@257,44 278,65 281,62 R28.1@308,62 ; R27.1@272,65 290,83 290,113 297,120 321,120 340,101 R22.2@340,95 ; R22.2@340,94 R22.2@340,95 ; R21.2@357.04,162.04 R21.2@357.5,162.5 ; R21.2@363,168 R21.2@357.5,162.5 ; C42.2@366,422 363.43,419.43 353.43,419.43 338,404 318,404 310.5,396.5 286.5,396.5 269,414 252,414 234,396 229,396 218,385 218,375 200,357 ; R22.2@340,95 357.5,112.5 R21.2@357.5,162.5
  other v2: 258,47 103,500
VDD_CPUFB: C5.2 R2.2 R26.1 U5.T10 | length 872.3
  Top1 w4: v2(60,683) 93,683 R2.2@95,681
  Top1 w10: U5.T10@391.18,197 v1(403.68,184.5)
  Power4 w4: v2(60,683) 81,662 81,498 66,483 66,390 143,313 177,313 195,295 195,237 246,186 332,186 370,148 397,148 411.43,162.43 411.43,176.16 403.68,183.91 v1(403.68,184.5)
VDD_SYS_3.3V: C6.2 C9.2 C25.2 C26.2 C27.2 C28.2 L3.2 L5.1 pad.65 R1.2 R6.2 R8.1 T5.0 U4.4 U5.G7 U5.G10 U5.G11 U5.G13 U5.G14 U5.G15 U5.H7 U5.H13 U5.H14 U5.J6 U5.J14 U5.J15 | length 2464.9
  Top1 w4: v2(560.06,873.4) v2(578.06,873.4) 620.6,873.4 639,855 766,855 804,817 804,798 809,793 809,695 820,684 948.31,684 982.31,650 1090.19,650 1119.19,679 T5.0@1168,679 1185,679 1194.71,669.29 pad.65@1220.47,669.29
  Top1 w5: L5.1@63,574 40.5,596.5 40.5,752.5 64,776 100,776 v2(118,794)
  Top1 w10: v1@271.72,364.08 283.44,375.8 288.44,375.8 U5.J6@288.82,376.18 ; U5.H7@314.41,401.77 v1(301.61,414.57) U5.G7@314.41,427.36 ; U5.G10@391.18,427.36 391.56,426.98 393.94,426.98 401.66,419.26 v1(403.28,419.26) 404.9,419.26 412.62,426.98 416.39,426.98 U5.G11@416.77,427.36 ; U5.G14@493.77,426.77 U5.H14@493.77,401.77 ; v1(506.67,386.28) 505.52,387.43 v1@505.52,387.93 ; U5.J15@519.77,376.18 U5.J15@519.36,376.18 ; U5.G15@519.77,427.36 U5.G15@519.23,427.36 ; U5.H13@468.77,401.77 U5.G13@468.77,427.36 ; U5.H13@468.77,401.77 v1@481.57,414.57 ; U5.H13@468.77,401.77 493.01,401.77 U5.H14@493.39,402.15 ; U5.G13@468.77,427.36 U5.G14@493.77,427.36 ; U5.G13@468.77,427.36 479.87,416.26 v1@481.57,414.57 ; v1@481.57,414.57 493.39,402.74 U5.H14@493.39,402.15 ; v1@481.57,414.57 493.39,426.39 493.39,426.98 U5.G14@493.77,427.36 ; U5.H14@493.39,402.15 U5.H14@493.77,401.77 ; U5.J14@493.77,376.18 U5.J15@519.36,376.18 ; U5.J14@493.77,376.18 v1@505.52,387.93 ; U5.J14@493.77,376.18 U5.H14@493.77,401.77 ; U5.H14@493.77,401.77 494.15,402.15 494.15,402.92 504.77,413.54 ; U5.H14@493.77,401.77 v1@505.52,390.02 ; U5.G14@493.77,427.36 493.77,426.82 494.77,425.82 494.77,425.74 504.77,415.74 ; U5.G14@493.77,427.36 506.5,427.36 ; 504.77,413.54 504.77,392.42 505.52,391.67 v1@505.52,390.02 ; 504.77,413.54 504.77,415.74 ; 504.77,413.54 505.88,414.64 ; 504.77,415.74 504.77,425.63 506.5,427.36 ; 504.77,415.74 505.88,414.64 ; v1@505.52,387.93 v1@505.52,390.02 ; v1@505.52,387.93 v1@506.57,388.98 ; v1@505.52,390.02 v1@506.57,388.98 ; 505.88,414.64 517.6,426.36 518.23,426.36 U5.G15@519.23,427.36 ; 506.5,427.36 U5.G15@519.23,427.36 ; v1@506.57,388.98 U5.J15@519.36,376.18
  Top1 w15: R6.2@390,762 389.42,762.58 389.42,793.44 383.14,799.72 v2(370,799.72) 370,808 394,832 C9.2@433,832 ; C25.2@469,712 v2(469,742)
  Power4 w15: v2(351,799.72) v2(370,799.72) v2(388,799.72) 453.72,799.72 527.4,873.4 v2(541.06,873.4) v2(560.06,873.4) v2(578.06,873.4)
  Bottom6 w15: v2(118,794) 123.72,799.72 v2(351,799.72) v2(370,799.72) v2(388,799.72) 450.96,799.72 469,781.69 v2(469,711.69)
  other v1: 271.72,370.08 478.87,415.26
  other v2: 63,571
VDD_USB_5V: J1.11 pad.66 pad.67 Q1.3 Q2.1 | length 745
  Top1 w15: Q2.1@876.59,818 876.59,775.41 899,753 899,740.15 908.15,731 949,731 961,719 961,698 990,669 v2(1023,669) v2(1041,669) v2(1041,669) Q1.3@1053,669
  Power4 w20: v2@1023,669.29 1059,669.29 1141,669.29 1180.37,708.66 ; pad.66@1220.47,708.66 1180.37,708.66 ; pad.67@1220.47,748.03 1219.03,746.59 1192.09,746.59 1180.37,734.87 1180.37,708.66
  Bottom6 w20: J1.11@1160,800 1160,756 1167.97,748.03 ; pad.66@1220.47,708.66 1207.34,708.66 1167.97,748.03 ; pad.67@1220.47,748.03 1167.97,748.03
  other v2: 1059,669
XIN: C32.2 U5.K2 Y1.1 | length 148.3
  Top1 w5: Y1.1@104.61,353.11 101,349.5 C32.2@101,309 126,334 169.87,334 U5.K2@186.46,350.59
XOUT: C31.1 U5.K1 Y1.3 | length 225.2
  Top1 w5: Y1.3@55.39,416.89 61,422.5 C31.1@61,465 80,446 80,399 95,384 115,384 148.41,350.59 U5.K1@160.87,350.59
pads on no net: U1.1 U5.A1 U5.A13 U5.A14 U5.A16 U5.A17 U5.AA2 U5.AA8 U5.AA9 U5.AA11 U5.AA12 U5.AA14 U5.AA15 U5.AA17 U5.AA18 U5.B1 U5.B2 U5.B17 U5.B18 U5.B19 U5.C1 U5.C2 U5.C14 U5.C17 U5.C18 U5.C19 U5.D8 U5.D13 U5.D17 U5.E14 U5.E16 U5.F3 U5.F10 U5.F13 U5.F16 U5.F17 U5.H4 U5.H16 U5.J3 U5.K4 U5.L2 U5.L5 U5.M1 U5.M3 U5.N1 U5.P3 U5.R2 U5.T3 U5.T4 U5.T5 U5.U4 U5.V5 U5.W9 U5.W12 U5.W15 U5.Y2 U5.Y7 U5.Y8 U5.Y9 U5.Y10 U5.Y11 U5.Y12 U5.Y13 U5.Y14 U5.Y15 U5.Y16 U5.Y17

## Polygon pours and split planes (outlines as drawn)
GND on Power4 "Top1-No Net" (solid, remove dead copper, pour order 30): 0,0 0,944.88 1220.47,944.88 1220.47,0
VCC-DRAM on Power4 "Top1-No Net" (solid, remove dead copper, pour order 28): 855,591 785,591 514,320 514,277 460,223 438,223 438,221 418,201 418,169 552,35 1146,36 1146,69 1193.45,69 1192.45,591 945,591 910,631 855,631
VDD-CPUX on Power4 "Top1-No Net" (solid, remove dead copper, pour order 6): 468.5,680 468.5,471 339,471 250,382 250,360 310,300 405,205 405,150.25 359.75,150.25 153.92,356.08 153.92,462 230.83,563.59 303.59,563.59 408,647.03 408,680 420,680
VDD_SYS_3.3V on Power4 "Top1-No Net" (solid, remove dead copper, pour order 4): 450,755 450,689 469,689 468,473 450,455 324.43,455 255,385.57 255.47,355 269,345 277,340 300,340 355,395 446.57,395 471,395 548,472 548,755
VDD1V2-SYS on Power4 "Top1-No Net" (solid, remove dead copper, pour order 8): 446,390 357,390 311,344 311,308 514,308 610,404 610,679 668,737 754,737 754,775 614,775 545,706 545,465 470,390
GND on Gnd3 "Top1-No Net" (solid, remove dead copper, pour order 12): 0,944.88 1220.47,944.88 1220.47,0 0,0
GND on Signal5 "Top1-No Net" (solid, remove dead copper, pour order 26): 0,944.88 1220.47,944.88 1220.47,0 0,0
GND on Top1 "Top1-No Net" (solid, remove dead copper, pour order 22): 0,944.88 1220.47,944.88 1220.47,0 0,0
GND on Bottom6 "Top1-No Net" (solid, remove dead copper, pour order 20): 0,944.88 1220.47,944.88 1220.47,0 0,0
GND on Signal2 "Top1-No Net" (solid, remove dead copper, pour order 24): 0,944.88 1220.47,944.88 1220.47,0 0,0

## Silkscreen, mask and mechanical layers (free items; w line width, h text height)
Top Overlay:
  lines w7: 29.53,55.47 29.53,889.53 55.35,915.35 1164.65,915.35 1190.95,889.06 1190.95,55.95 1164.53,29.53 55.47,29.53 29.53,55.47
  text "- Ver 1.1 -" at 1024,705 h40
  text "3V3" at 1106,671 h30
  text "1V1" at 1106,649 h30
  text "1V2" at 1106,627 h30
  text "1V5" at 1106,605 h30
  text "CPU" at 703,215 h80 r270
  text "DDR" at 832,215 h80 r90
Bottom Overlay:
  rectangle: 885,610 1185,635
  lines w7: 535,520 130,520 130,43.5 536,43.5 536,520
  text "[Project Quantum]" at 813,832 h90
  text "UART0_TX" at 935,765 h30 r90
  text "SD_CLK" at 985,765 h30 r90
  text "SD_CMD" at 1035,765 h30 r90
  text "SD_DET" at 1085,765 h30 r90
  text "GND" at 1135,765 h30 r90
  text "VDD_5V" at 1185,765 h30 r90
  text "2020.1.5" at 293,762 h50
  text "By Pengzhihui" at 812,762 h50
  text "UART0_RX" at 935,620 h30 r90
  text "SD_D3" at 985,620 h30 r90
  text "SD_D2" at 1035,620 h30 r90
  text "SD_D1" at 1085,620 h30 r90
  text "SD_D0" at 1135,620 h30 r90
  text "VDD_USB" at 1185,620 h30 r90
Top Solder:
  drawing of 296 lines, arcs and shapes, not listed
  text "[Quark]" at 911,859 h60
  text "Core+" at 911,800 h40
  text "LINUX" at 1108,796 h30
  text "pengzhihui.xyz" at 913,751 h45
Mechanical 1:
  the board outline again, w5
